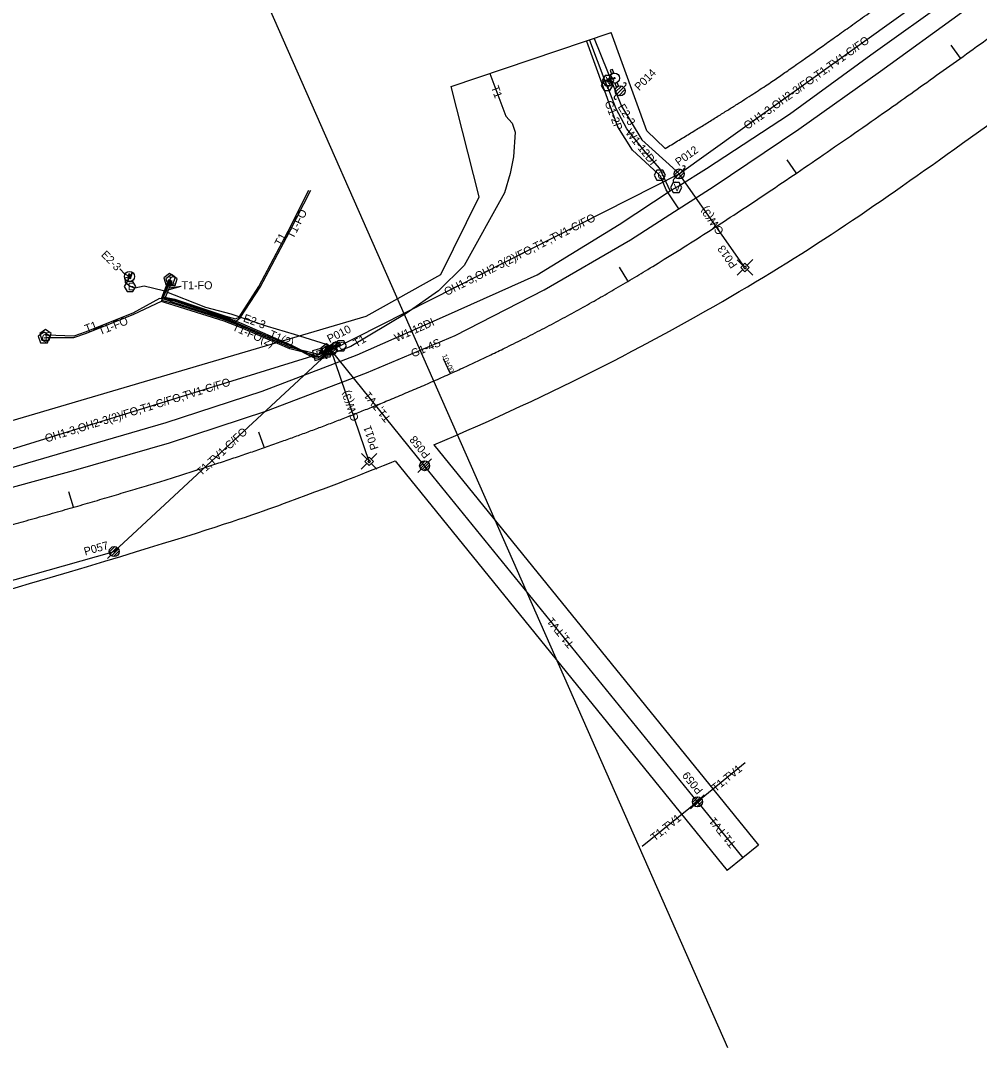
# Model space of a CAD drawing. Extents: x 1991878 to 2008544, y 770238 to 1141211.
# Drawn here: x 2003698 to 2004177, y 1138505 to 1139018 of the extents above; entities that cross this region are included whole.
import ezdxf

# ---------------------------------------------------------------- set-up
doc = ezdxf.new("R2010")
doc.units = 0
for name, color, linetype in [('RD_EX_SU_Elec', 7, 'Continuous'), ('RD_EX_SU_Gas', 7, 'Continuous'), ('RD_EX_SU_H2O', 7, 'Continuous'), ('RD_EX_SU_Ovhd', 7, 'Continuous'), ('RD_EX_SU_Pole', 7, 'Continuous'), ('RD_EX_SU_SwpLmt', 7, 'Continuous'), ('RD_EX_SU_Telecom', 7, 'Continuous'), ('RD_EX_SU_TX_Elec', 7, 'Continuous'), ('RD_EX_SU_TX_Gas', 7, 'Continuous'), ('RD_EX_SU_TX_H2O', 7, 'Continuous'), ('RD_EX_SU_TX_Ovhd', 7, 'Continuous'), ('RD_EX_SU_TX_Pole', 7, 'Continuous'), ('RD_EX_SU_TX_Telecom', 7, 'Continuous'), ('RD_HC_Cl', 7, 'Continuous')]:
    doc.layers.add(name, color=color, linetype=linetype)

msp = doc.modelspace()

# ---------------------------------------------------------------- linework, layer by layer
at = {"layer": 'RD_EX_SU_Elec'}
for points in [[(2003984.24, 1139008.89), (2003997.94, 1138974.99), (2004008.04, 1138958.25), (2004025.35, 1138942.63), (2004026.75, 1138941.13)], [(2003752.18, 1138889.88), (2003749.86, 1138891.02), (2003747.25, 1138893.73)], [(2003752.45, 1138884.91), (2003750.23, 1138886.67), (2003750.02, 1138889.25), (2003752.18, 1138889.88)], [(2003852.91, 1138853.11), (2003852.84, 1138854.27), (2003850.64, 1138855.87), (2003834.66, 1138860.91), (2003821.07, 1138864.85), (2003803.03, 1138871.05), (2003790.25, 1138874.49), (2003769.15, 1138882.68), (2003759.55, 1138885.08), (2003754.74, 1138884.01), (2003752.45, 1138884.91)]]:
    msp.add_lwpolyline(points, dxfattribs=at)
for points in [[(2003755.33, 1138884.91), (2003753.89, 1138887.41), (2003751, 1138887.41), (2003749.56, 1138884.91), (2003751, 1138882.41), (2003753.89, 1138882.41)], [(2003753.56, 1138891.94), (2003752.56, 1138888.49), (2003752.06, 1138890.37), (2003751.29, 1138887.54), (2003751.99, 1138891.45), (2003752.55, 1138889.51)]]:
    msp.add_lwpolyline(points, close=True, dxfattribs=at)
msp.add_circle((2003752.18, 1138889.88), 2.55, dxfattribs=at)
at = {"layer": 'RD_EX_SU_Gas'}
for points in [[(2003677.03, 1138780.22), (2003724.13, 1138793.01), (2003772.14, 1138806.72), (2003820.27, 1138822.65), (2003870.57, 1138841.78), (2003914.88, 1138860.46), (2003959.38, 1138883.31), (2004002.39, 1138908.27), (2004024.47, 1138922.38), (2004043.8, 1138934.66), (2004086.62, 1138963.57), (2004127.39, 1138992.43), (2004167.83, 1139021.75)], [(2004026.67, 1138923.78), (2004020.29, 1138933.22), (2004017.47, 1138940.09), (2004016.2, 1138941.24), (2004003.4, 1138952.96), (2003996.2, 1138964.72), (2003993.06, 1138972.92), (2003980.57, 1139007.33)]]:
    msp.add_lwpolyline(points, dxfattribs=at)
msp.add_lwpolyline([(2004018.53, 1138937.98), (2004019.97, 1138940.48), (2004018.53, 1138942.98), (2004015.64, 1138942.98), (2004014.2, 1138940.48), (2004015.64, 1138937.98)], close=True, dxfattribs=at)
at = {"layer": 'RD_EX_SU_H2O'}
for p, q in [((2003993.44, 1138993.4), (2003992.26, 1138992.97)), ((2003992.26, 1138992.97), (2003992.95, 1138991.07)), ((2003994.12, 1138991.54), (2003993.44, 1138993.4)), ((2003991.94, 1138988.86), (2003990.4, 1138988.3)), ((2003990.4, 1138988.3), (2003990.83, 1138987.12)), ((2003990.83, 1138987.12), (2003992.34, 1138987.67)), ((2003994.6, 1138986.53), (2003995.27, 1138984.68)), ((2003995.27, 1138984.68), (2003996.45, 1138985.11)), ((2003996.45, 1138985.11), (2003995.8, 1138986.91))]:
    msp.add_line(p, q, dxfattribs=at)
for points in [[(2003687.76, 1138792.8), (2003723.04, 1138803.19), (2003770.48, 1138816.89), (2003818.48, 1138832.55), (2003865.98, 1138850.69), (2003910, 1138870.23), (2003955.91, 1138890.72), (2003996.73, 1138915.93), (2004022.22, 1138932.65), (2004026.54, 1138935.27), (2004040.37, 1138943.8), (2004081.95, 1138971.07), (2004122.45, 1139000.61), (2004162.73, 1139029.52)], [(2004022.22, 1138932.65), (2004017.19, 1138943.85), (2004009.76, 1138952.18), (2004000.58, 1138963.7), (2003995.25, 1138973.73), (2003991.26, 1138983.97), (2003989.85, 1138987.48), (2003982.15, 1139007.86)], [(2003994.45, 1138989.04), (2003993.52, 1138988.79), (2003990.45, 1138987.65), (2003989.87, 1138987.41)]]:
    msp.add_lwpolyline(points, dxfattribs=at)
for points in [[(2003994.13, 1138987.88), (2003992.69, 1138990.38), (2003989.8, 1138990.38), (2003988.36, 1138987.88), (2003989.8, 1138985.38), (2003992.69, 1138985.38)], [(2003993.56, 1138985.38), (2003992.11, 1138987.88), (2003989.23, 1138987.88), (2003987.78, 1138985.38), (2003989.23, 1138982.88), (2003992.11, 1138982.88)], [(2004028.16, 1138934.34), (2004026.71, 1138936.84), (2004023.83, 1138936.84), (2004022.38, 1138934.34), (2004023.83, 1138931.84), (2004026.71, 1138931.84)]]:
    msp.add_lwpolyline(points, close=True, dxfattribs=at)
for radius in [2.52, 0.315]:
    msp.add_circle((2003994.45, 1138989.04), radius, dxfattribs=at)
for start, end in [(97.6184, 126.5947), (184.1789, 213.1462), (273.2721, 302.2484)]:
    msp.add_arc((2003994.45, 1138989.04), 2.52, start, end, dxfattribs=at)
at = {"layer": 'RD_EX_SU_Ovhd'}
for p, q in [((2004026.75, 1138941.13), (2004156.05, 1139033.8)), ((2003852.91, 1138853.11), (2004026.75, 1138941.13)), ((2004059.65, 1138894.4), (2004026.75, 1138941.13)), ((2003662.8, 1138794.22), (2003852.91, 1138853.11)), ((2003744.54, 1138752.48), (2003852.91, 1138853.11)), ((2003899.62, 1138795.38), (2003852.91, 1138853.11)), ((2003871.88, 1138797.53), (2003852.91, 1138853.11)), ((2004035.9, 1138627.44), (2003899.62, 1138795.38)), ((2003453.51, 1138670.84), (2003744.54, 1138752.48)), ((2004059.82, 1138646.85), (2004035.9, 1138627.44)), ((2004035.9, 1138627.44), (2004008.31, 1138605.05)), ((2004035.9, 1138627.44), (2004058.58, 1138599.49))]:
    msp.add_line(p, q, dxfattribs=at)
at = {"layer": 'RD_EX_SU_Pole'}
for p, q in [((2003997.91, 1138985.04), (2003994.84, 1138981.98)), ((2004000.09, 1138985.46), (2003999.03, 1138984.4)), ((2003995.49, 1138980.86), (2003994.43, 1138979.8)), ((2003999.03, 1138984.4), (2003995.49, 1138980.86)), ((2003999.67, 1138983.28), (2003996.61, 1138980.22)), ((2004028.52, 1138942.9), (2004029.58, 1138943.96)), ((2004023.92, 1138938.3), (2004024.98, 1138939.36)), ((2004024.34, 1138940.48), (2004027.4, 1138943.55)), ((2004024.98, 1138939.36), (2004028.52, 1138942.9)), ((2004026.11, 1138938.72), (2004029.17, 1138941.78)), ((2004058.59, 1138895.46), (2004055.76, 1138898.29)), ((2004060.68, 1138895.51), (2004063.52, 1138898.35)), ((2004058.54, 1138893.35), (2004055.71, 1138890.52)), ((2004060.71, 1138893.34), (2004063.54, 1138890.51)), ((2003850.08, 1138850.28), (2003851.14, 1138851.34)), ((2003850.49, 1138852.46), (2003853.55, 1138855.53)), ((2003851.14, 1138851.34), (2003854.67, 1138854.88)), ((2003852.26, 1138850.7), (2003855.32, 1138853.76)), ((2003854.67, 1138854.88), (2003855.73, 1138855.94)), ((2003870.82, 1138798.6), (2003867.99, 1138801.42)), ((2003872.9, 1138798.65), (2003875.74, 1138801.49)), ((2003870.77, 1138796.49), (2003867.94, 1138793.66)), ((2003872.94, 1138796.47), (2003875.77, 1138793.65)), ((2003897.14, 1138795.05), (2003899.95, 1138797.86)), ((2003897.52, 1138794.01), (2003900.98, 1138797.48)), ((2003898.22, 1138793.3), (2003901.7, 1138796.77)), ((2003899.24, 1138792.9), (2003902.09, 1138795.76)), ((2003901.39, 1138797.15), (2003903.04, 1138798.8)), ((2003896.2, 1138791.95), (2003897.85, 1138793.61)), ((2003901.14, 1138793.39), (2003901.61, 1138793.85)), ((2003742.06, 1138752.15), (2003744.87, 1138754.96)), ((2003742.44, 1138751.12), (2003745.9, 1138754.58)), ((2003743.14, 1138750.41), (2003746.61, 1138753.88)), ((2003746.31, 1138754.25), (2003747.96, 1138755.91)), ((2003741.11, 1138749.06), (2003742.77, 1138750.71)), ((2003744.16, 1138750.01), (2003747.01, 1138752.86)), ((2003746.06, 1138750.5), (2003746.52, 1138750.96)), ((2004037.67, 1138629.21), (2004039.32, 1138630.86)), ((2004032.48, 1138624.01), (2004034.13, 1138625.67)), ((2004033.42, 1138627.11), (2004036.23, 1138629.92)), ((2004033.8, 1138626.07), (2004037.26, 1138629.54)), ((2004034.5, 1138625.36), (2004037.98, 1138628.83)), ((2004035.52, 1138624.96), (2004038.37, 1138627.82)), ((2004037.42, 1138625.45), (2004037.89, 1138625.91))]:
    msp.add_line(p, q, dxfattribs=at)
for points in [[(2004059.65, 1138892.28), (2004061.77, 1138894.4), (2004059.65, 1138896.52), (2004057.53, 1138894.4)], [(2004059.65, 1138893.69), (2004060.36, 1138894.4), (2004059.65, 1138895.1), (2004058.95, 1138894.4)], [(2003871.88, 1138795.41), (2003874, 1138797.54), (2003871.88, 1138799.66), (2003869.76, 1138797.53)], [(2003871.88, 1138796.83), (2003872.59, 1138797.54), (2003871.88, 1138798.24), (2003871.17, 1138797.53)]]:
    msp.add_lwpolyline(points, close=True, dxfattribs=at)
for centre in [(2003997.26, 1138982.63), (2004026.75, 1138941.13), (2003852.91, 1138853.11), (2003899.62, 1138795.38), (2003744.54, 1138752.48), (2004035.9, 1138627.44)]:
    msp.add_circle(centre, 2.5, dxfattribs=at)
for centre, start, end in [((2003999.56, 1138985.99), 315.0116, 135.0116), ((2003994.96, 1138979.27), 135.0116, 315.0116), ((2004029.05, 1138944.49), 315.0116, 135.0116), ((2004024.45, 1138937.77), 135.0116, 315.0116), ((2003855.2, 1138856.47), 315.0116, 135.0116), ((2003850.61, 1138849.75), 135.0116, 315.0116)]:
    msp.add_arc(centre, 0.75, start, end, dxfattribs=at)
at = {"layer": 'RD_EX_SU_SwpLmt'}
for p, q in [((2004010.62, 1138962.61), (2003992.79, 1139011.78)), ((2004019.84, 1138953.87), (2004010.62, 1138962.61)), ((2003427.15, 1138739.5), (2003870.35, 1138870.15)), ((2003884.84, 1138797.79), (2004050.81, 1138593.19))]:
    msp.add_line(p, q, dxfattribs=at)
for points in [[(2003912.93, 1138984.76), (2003992.79, 1139011.78)], [(2003870.35, 1138870.15), (2003907.69, 1138890.92), (2003926.8, 1138929.65), (2003912.93, 1138984.76)], [(2003904.13, 1138805.76), (2004066.34, 1138605.79), (2004050.81, 1138593.19)]]:
    msp.add_lwpolyline(points, dxfattribs=at)
for points, degree in [([(2003904.13, 1138805.76), (2003963.45, 1138830.79), (2004071.64, 1138887.18), (2004169.39, 1138957.24), (2004278.15, 1139035.08), (2004310.69, 1139058.54)], 3), ([(2004019.84, 1138953.87), (2004060.69, 1138978.54), (2004097.42, 1139004.2), (2004148.08, 1139040.37)], 2), ([(2002961.67, 1138524.77), (2003135.44, 1138573.78), (2003750.13, 1138748.44), (2003835.13, 1138778.08), (2003876.89, 1138794.57), (2003884.84, 1138797.79)], 3)]:
    msp.add_open_spline(points, degree=degree, dxfattribs=at)
at = {"layer": 'RD_EX_SU_Telecom'}
for points in [[(2003932.25, 1138991.29), (2003940.12, 1138969.95), (2003943.32, 1138966.58), (2003944.79, 1138962.06), (2003944.08, 1138949.75), (2003942.37, 1138941.41), (2003939.54, 1138931.71), (2003919.31, 1138895.36), (2003906.55, 1138882.79), (2003890.4, 1138871.5), (2003862.67, 1138854.95), (2003852.67, 1138851.14), (2003851.67, 1138851.36), (2003850.6, 1138852.14)], [(2003772.11, 1138888.35), (2003771.74, 1138887.37), (2003768.98, 1138879.72), (2003774.79, 1138878.6), (2003800.25, 1138870.15), (2003805.16, 1138868.74), (2003807, 1138869.63), (2003816.8, 1138884.9), (2003831.4, 1138912.54), (2003841.76, 1138932.96)], [(2003773.17, 1138887.87), (2003773.12, 1138886.84), (2003769.63, 1138878.62), (2003774.44, 1138876.98), (2003799.58, 1138868.93), (2003804.36, 1138866.83), (2003807.51, 1138869.24), (2003817.46, 1138884.65), (2003832.07, 1138912.3), (2003842.73, 1138933.08)], [(2003850.6, 1138852.14), (2003849.81, 1138851.37), (2003847.12, 1138849.72), (2003844.74, 1138849.72), (2003832.96, 1138855.64), (2003808.38, 1138866.24), (2003799.96, 1138869.79), (2003774.76, 1138878.05), (2003768.26, 1138879.24), (2003771.43, 1138887.5), (2003772.11, 1138888.35)], [(2003846.57, 1138850.97), (2003832.41, 1138854.42), (2003807.82, 1138865.1), (2003799.59, 1138868.22), (2003774.53, 1138876.29), (2003768.37, 1138877.93), (2003772.52, 1138886.99), (2003773.17, 1138887.87)], [(2003846.57, 1138850.97), (2003845.41, 1138850.37), (2003832.19, 1138853.77), (2003807.6, 1138864.43), (2003799.5, 1138867.58), (2003774.42, 1138875.42), (2003768.02, 1138877.39), (2003754.21, 1138870.86), (2003730.43, 1138861.47), (2003724.24, 1138859.28), (2003710.8, 1138859.22), (2003709.46, 1138859.11)], [(2003852.91, 1138853.11), (2003850.6, 1138852.14), (2003850.28, 1138851.09), (2003847.45, 1138848.96), (2003844.56, 1138849.09), (2003832.75, 1138855.04), (2003808.12, 1138865.67), (2003799.84, 1138869.32), (2003774.66, 1138877.57), (2003767.12, 1138878.92), (2003753.85, 1138871.52), (2003730.03, 1138862.06), (2003724.41, 1138860.04), (2003710.92, 1138860.57), (2003710.18, 1138860.5)], [(2003857.76, 1138855.31), (2003857.19, 1138856.89), (2003853.84, 1138856.73), (2003850.92, 1138854.02), (2003850.63, 1138853.18)], [(2003852.91, 1138853.11), (2003850.86, 1138854.34), (2003849.63, 1138854.55), (2003847.25, 1138852.27), (2003846.57, 1138850.97)], [(2003846.57, 1138850.97), (2003847.49, 1138851.81), (2003849.89, 1138853.3), (2003850.63, 1138853.18)], [(2003850.63, 1138853.18), (2003849.86, 1138852.53), (2003847.63, 1138851.4), (2003846.57, 1138850.97)], [(2003852.91, 1138853.11), (2003851.65, 1138852.99), (2003850.63, 1138853.18)], [(2003857.76, 1138855.31), (2003856.56, 1138856.38), (2003854.03, 1138856.13), (2003851.51, 1138854.77), (2003852.91, 1138853.11)], [(2003857.76, 1138855.31), (2003856.05, 1138855.81), (2003851.81, 1138854.49), (2003851.97, 1138853.54), (2003852.91, 1138853.11)], [(2003857.76, 1138855.31), (2003855.99, 1138855.15), (2003852.35, 1138854.03), (2003852.91, 1138853.11)]]:
    msp.add_lwpolyline(points, dxfattribs=at)
for points in [[(2003772.11, 1138891.35), (2003769.25, 1138889.27), (2003770.34, 1138885.92), (2003773.87, 1138885.92), (2003774.96, 1138889.27)], [(2003773.17, 1138890.87), (2003770.32, 1138888.8), (2003771.41, 1138885.44), (2003774.93, 1138885.44), (2003776.02, 1138888.8)], [(2003709.46, 1138862.11), (2003706.6, 1138860.04), (2003707.69, 1138856.68), (2003711.22, 1138856.68), (2003712.31, 1138860.04)], [(2003710.18, 1138863.5), (2003707.33, 1138861.43), (2003708.42, 1138858.08), (2003711.94, 1138858.08), (2003713.03, 1138861.43)], [(2003860.64, 1138855.31), (2003859.2, 1138857.81), (2003856.31, 1138857.81), (2003854.87, 1138855.31), (2003856.31, 1138852.81), (2003859.2, 1138852.81)], [(2003848.33, 1138854.04), (2003843.51, 1138852.72), (2003844.82, 1138847.9), (2003849.64, 1138849.22)], [(2003850.6, 1138855.14), (2003847.74, 1138853.07), (2003848.83, 1138849.71), (2003852.36, 1138849.71), (2003853.45, 1138853.07)], [(2003850.63, 1138856.18), (2003847.78, 1138854.1), (2003848.87, 1138850.75), (2003852.4, 1138850.75), (2003853.49, 1138854.1)]]:
    msp.add_lwpolyline(points, close=True, dxfattribs=at)
at = {"layer": 'RD_EX_SU_TX_Telecom'}
for p in [(2003770.74, 1138883.11), (2003772.04, 1138884.29)]:
    msp.add_line(p, (2003778.04, 1138885), dxfattribs=at)
at = {"layer": 'RD_HC_Cl'}
for p, q in [((2003757.04, 1139171.38), (2004050.9, 1138504.71)), ((2004162.44, 1139005.46), (2004167.09, 1138998.95)), ((2004080.64, 1138948.27), (2004085.13, 1138941.65)), ((2003996.85, 1138894.63), (2004000.92, 1138887.74)), ((2003908.92, 1138849.01), (2003912.2, 1138841.72)), ((2003816.68, 1138812.32), (2003819.32, 1138804.76)), ((2003721.71, 1138782.47), (2003723.93, 1138774.79))]:
    msp.add_line(p, q, dxfattribs=at)
msp.add_open_spline([(2002937.27, 1138556.06), (2003081.12, 1138596.24), (2003224.54, 1138636.27), (2003324.8, 1138664.72), (2003440.8, 1138697.76), (2003610.3, 1138743.13), (2003753.45, 1138782.34), (2003851.96, 1138815.09), (2003945.32, 1138855.48), (2004023.07, 1138899.74), (2004117.46, 1138962.96), (2004239.69, 1139051.13), (2004401.3, 1139168.16), (2004522.74, 1139256.47), (2004724.1, 1139402.13), (2005003.72, 1139590.96), (2005189.76, 1139724.82), (2005285.27, 1139787.25)], degree=2, dxfattribs=at)

# ---------------------------------------------------------------- texts
at = {"layer": 'RD_EX_SU_Elec'}
msp.add_text('E', height=3.75, rotation=360, dxfattribs=at).set_placement((2003751.31, 1138883.03))
at = {"layer": 'RD_EX_SU_Gas'}
msp.add_text('G', height=3.75, dxfattribs=at).set_placement((2004015.93, 1138938.61))
at = {"layer": 'RD_EX_SU_H2O'}
for p in [(2003989.46, 1138983.5), (2003990.04, 1138986), (2004024.06, 1138932.46)]:
    msp.add_text('V', height=3.75, dxfattribs=at).set_placement(p)
at = {"layer": 'RD_EX_SU_Telecom'}
for s, height, p in [('T', 3.75, (2003770.88, 1138886.12)), ('C', 4, (2003771.94, 1138885.87)), ('T', 3.75, (2003708.95, 1138858.28)), ('C', 4, (2003708.23, 1138857.11)), ('C', 3.75, (2003856.61, 1138853.44)), ('T', 3.75, (2003849.37, 1138849.91)), ('C', 4, (2003849.4, 1138851.18))]:
    msp.add_text(s, height=height, dxfattribs=at).set_placement(p)
msp.add_text('F', height=4, rotation=15.2395, dxfattribs=at).set_placement((2003846.01, 1138848.74))
at = {"layer": 'RD_EX_SU_TX_Elec'}
for rotation, p in [(301.1084, (2003995.91, 1138974.6)), (314.0099, (2003737.7, 1138900.53)), (340.3039, (2003808.65, 1138867.51))]:
    msp.add_text('E2-3', height=4, rotation=rotation, dxfattribs=at).set_placement(p)
at = {"layer": 'RD_EX_SU_TX_Gas'}
for s, rotation, p in [('G1-2P', 291.0208, (2003989.41, 1138976.88)), ('G1-4S', 22.8551, (2003893.83, 1138849.39))]:
    msp.add_text(s, height=4, rotation=rotation, dxfattribs=at).set_placement(p)
at = {"layer": 'RD_EX_SU_TX_H2O'}
for rotation, p in [(308.5493, (2003999.68, 1138961.63)), (23.9384, (2003885.57, 1138857.17))]:
    msp.add_text('W1-12DI', height=4, rotation=rotation, dxfattribs=at).set_placement(p)
at = {"layer": 'RD_EX_SU_TX_Ovhd'}
for s, rotation, p in [('OH1-3,OH2-3/FO,T1,TV1-C/FO', 35.6295, (2004060.79, 1138963.07)), ('GW(3)', 125.1458, (2004049.36, 1138912.49)), ('OH1-3,OH2-3(2)/FO,T1-,TV1-C/FO', 26.8532, (2003910.61, 1138880.14)), ('OH1-3,OH2-3(2)/FO,T1-C/FO,TV1-C/FO', 17.2125, (2003710.64, 1138806.95)), ('GW(3)', 108.849, (2003866.85, 1138818.47)), ('T1,TV1', 128.9773, (2003883.02, 1138819.08)), ('T1,TV1-C/FO', 42.8796, (2003787.92, 1138790.04)), ('T1,TV1', 129.0589, (2003974.52, 1138706.25)), ('T1,TV1', 39.0589, (2004044.96, 1138632.21)), ('T1,TV1', 39.0589, (2004014.54, 1138607.53)), ('T1,TV1', 129.0589, (2004055.48, 1138606.48))]:
    msp.add_text(s, height=4, rotation=rotation, dxfattribs=at).set_placement(p)
at = {"layer": 'RD_EX_SU_TX_Pole'}
for s, rotation, p in [('P014', 45.0116, (2004006.77, 1138982.42)), ('P012', 35.6295, (2004026.55, 1138944.96)), ('P013', 125.1458, (2004056.08, 1138895.76)), ('P010', 26.8532, (2003852.12, 1138856.67)), ('P011', 108.849, (2003876.62, 1138804.03)), ('P058', 128.977, (2003902.69, 1138801.05)), ('P057', 15.6703, (2003730.01, 1138750.48)), ('P059', 129.0589, (2004038.95, 1138633.26))]:
    msp.add_text(s, height=4, rotation=rotation, dxfattribs=at).set_placement(p)
at = {"layer": 'RD_EX_SU_TX_Telecom'}
for s, rotation, p in [('T1', 290.2374, (2003932.66, 1138984.45)), ('T1-FO', 62.8267, (2003833.99, 1138908.43)), ('T1', 62.1704, (2003827.89, 1138904.67)), ('T1-FO', 359.9993, (2003778.16, 1138883.53)), ('T1', 21.6589, (2003730.7, 1138861.74)), ('T1-FO', 21.5477, (2003737.48, 1138860.53)), ('T1-FO(2)', 336.5817, (2003803.18, 1138863.22)), ('T1(2)', 336.6404, (2003821.52, 1138859.57)), ('T1', 30.831, (2003865.4, 1138854.36))]:
    msp.add_text(s, height=4, rotation=rotation, dxfattribs=at).set_placement(p)
at = {"layer": 'RD_HC_Cl'}
msp.add_text('10+00', height=2.5, rotation=294.2757, dxfattribs=at).set_placement((2003908.27, 1138850.43))

doc.saveas('drawing.dxf')
